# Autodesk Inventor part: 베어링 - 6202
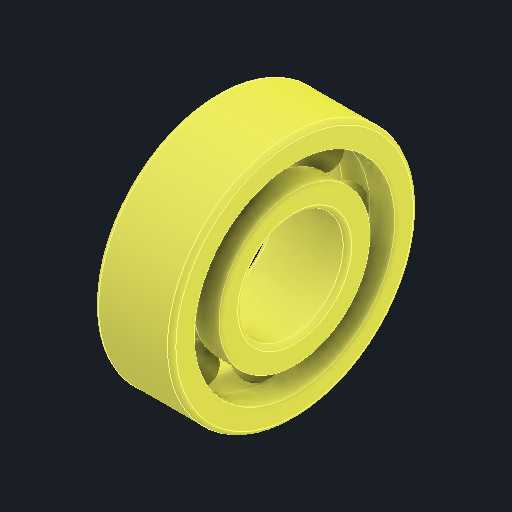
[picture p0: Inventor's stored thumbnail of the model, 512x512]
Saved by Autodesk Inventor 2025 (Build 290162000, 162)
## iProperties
Created: 2025-08
Part Number: 베어링 - 6202
Material: 강, 연강
Description: 깊은 그루브 볼 베어링
Document SubType Name: Modeling
Designer: infra027
Density: 7.86 g/cm^3
Appearance: 기본값
Author: jhkim
Sending System: Autodesk Inventor 2026
Preprocessor: ST-DEVELOPER v20.1
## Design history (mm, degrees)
feature "Solid1"
feature "Solid1:1"
feature "Solid1:2"
feature "Solid1:3"
feature "Solid1:4"
feature "Solid1:5"
feature "Solid1:6"
feature "Solid1:7"
feature "Solid1:8"
feature "Solid1:9"
node "솔리드1"
node "솔리드2"
node "솔리드3"
node "솔리드4"
node "솔리드5"
node "솔리드6"
node "솔리드7"
node "솔리드8"
node "솔리드9"
node "솔리드10"
